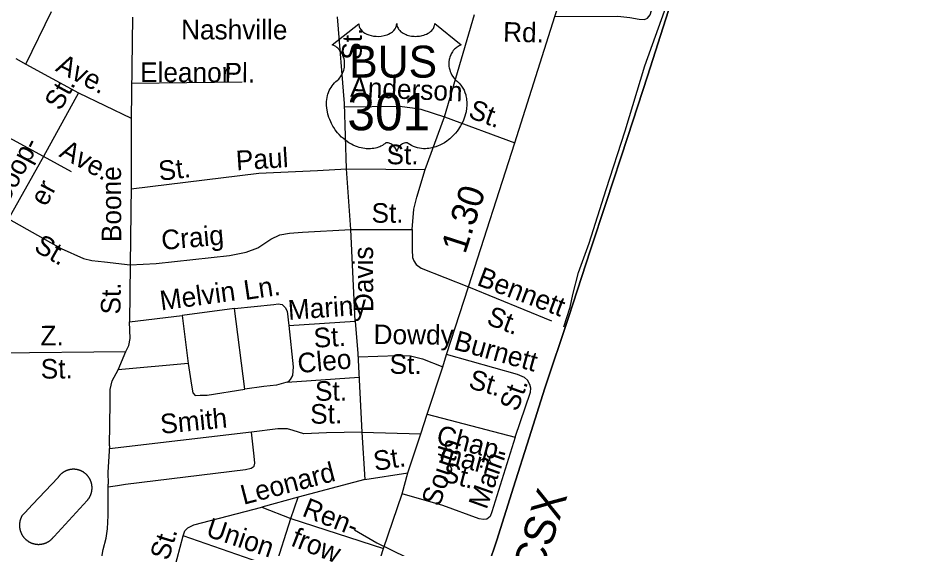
# Model space of a CAD drawing. Extents: x 2220236 to 2384410, y 720751 to 894131.
# Drawn here: x 2351588 to 2355954, y 791757 to 794328 of the extents above; entities that cross this region are included whole.
import ezdxf

# ---------------------------------------------------------------- set-up
doc = ezdxf.new("R2010")
doc.units = 0
doc.layers.add('Default', color=7, linetype='Continuous')

msp = doc.modelspace()

# ---------------------------------------------------------------- linework, layer by layer
at = {"layer": 'Default'}
for p, q in [((2351626.7, 794104.3), (2351750.7, 794358.9)), ((2353169.6, 793913.4), (2353137, 794334.5)), ((2353654.2, 793849.6), (2353800.3, 794344.9)), ((2352142.5, 794331.5), (2352136.8, 793843)), ((2351578.4, 794131.9), (2351626.7, 794104.3)), ((2351626.7, 794104.3), (2351880.9, 793965.7)), ((2351880.9, 793965.7), (2351711.2, 793658)), ((2351880.9, 793965.7), (2352136.8, 793843)), ((2353179.5, 793597.7), (2353169.6, 793913.4)), ((2351711.2, 793658), (2351402, 793824)), ((2352136.8, 793843), (2352136.8, 793515.1)), ((2353561.4, 793594.3), (2353654.2, 793849.6)), ((2353654.2, 793849.6), (2353995.7, 793723.4)), ((2351711.2, 793658), (2351541.6, 793355.6)), ((2351848.1, 793583.7), (2351711.2, 793658)), ((2353200.9, 793304), (2353179.5, 793597.7)), ((2353179.5, 793597.7), (2353561.4, 793594.3)), ((2352136.8, 793515.1), (2352132.1, 793132.4)), ((2353200.9, 793304), (2353498.8, 793303.6)), ((2353222.2, 792860.5), (2353200.9, 793304)), ((2352132.1, 793132.4), (2352128.6, 792857.3)), ((2353771.1, 793026.6), (2354173.9, 792861.9)), ((2352637.6, 792921.5), (2352383.7, 792888.1)), ((2352688.1, 792529.8), (2352637.6, 792921.5)), ((2352128.6, 792857.3), (2352383.7, 792888.1)), ((2352383.7, 792888.1), (2352413.5, 792654.2)), ((2352900.5, 792838.6), (2353222.2, 792860.5)), ((2353222.2, 792860.5), (2353235.2, 792703.4)), ((2351348.7, 792706), (2352110.3, 792713.1)), ((2352073.5, 792624.7), (2352110.3, 792713.1)), ((2353235.2, 792703.4), (2353254.7, 792323)), ((2352413.5, 792654.2), (2352073.5, 792624.7)), ((2352892.1, 792565.1), (2353241.1, 792588.8)), ((2353571.5, 792408.8), (2353996.8, 792297.9)), ((2352719.1, 792323), (2352030.9, 792241.7)), ((2353254.7, 792323), (2353540.8, 792314.5)), ((2353254.7, 792323), (2353269.5, 792093.3)), ((2353269.5, 792093.3), (2353477, 792125.8)), ((2353269.5, 792093.3), (2352946.4, 792008.2)), ((2351762.8, 791817.3), (2351922.8, 791990.9)), ((2352946.4, 792008.2), (2352769.1, 791959.2)), ((2352910.7, 791904), (2352946.4, 792008.2)), ((2352769.1, 791959.2), (2352910.7, 791904)), ((2352833.8, 791666.1), (2352910.7, 791904)), ((2352910.7, 791904), (2353358.8, 791758.5)), ((2352321.5, 791572.9), (2352389, 791820.9)), ((2352833.8, 791666.1), (2352389, 791820.9))]:
    msp.add_line(p, q, dxfattribs=at)
for points in [[(2353828.2, 791561.1), (2353908, 791798.6), (2353988.7, 792056.1), (2354064.7, 792295.5), (2354141.6, 792535.9), (2354255.5, 792877.9), (2354362.8, 793205.7), (2354437.8, 793434.7), (2354543.2, 793754.9), (2354639.1, 794046.6), (2354740.7, 794364.8), (2354855.5, 794713.5), (2354972.3, 795071.7), (2355085.3, 795428), (2355185, 795733), (2355317, 796125.4), (2355452.7, 796546.3), (2355542.9, 796832.3), (2355661.6, 797196.2), (2355741.4, 797441.3), (2355954, 798148.2)], [(2355954, 798148.2), (2355741.4, 797441.3), (2355661.6, 797196.2), (2355542.9, 796832.3), (2355452.7, 796546.3), (2355317, 796125.4), (2355185, 795733), (2355085.3, 795428), (2354972.3, 795071.7), (2354855.5, 794713.5), (2354740.7, 794364.8), (2354639.1, 794046.6), (2354543.2, 793754.9), (2354437.8, 793434.7), (2354362.8, 793205.7), (2354255.5, 792877.9), (2354141.6, 792535.9), (2354064.7, 792295.5), (2353988.7, 792056.1), (2353908, 791798.6), (2353828.2, 791561.1)], [(2353000.4, 790646), (2353049.1, 790801), (2353123.6, 791038.5), (2353207.2, 791284.8), (2353280.4, 791511.5), (2353358.8, 791758.5), (2353450.2, 792023.5), (2353477, 792125.8), (2353540.8, 792314.5), (2353571.5, 792408.8), (2353646.8, 792639.5), (2353664, 792697.9), (2353771.1, 793026.6), (2353995.7, 793723.4), (2354190.2, 794335.6), (2354323.4, 794739), (2354464.8, 795188), (2354608.5, 795632.2), (2354625.9, 795670.4), (2354758.9, 796083.8), (2354776.2, 796150.1), (2354878.2, 796485.2), (2354997.8, 796838.4), (2355117.9, 797165.9)], [(2354233.2, 792832.6), (2354233.3, 792833.1), (2354263.1, 792927), (2354276.4, 792989.2), (2354305, 793095.4), (2354355.2, 793237.9), (2354438.1, 793496.8), (2354530.7, 793781.9), (2354624.9, 794096.9), (2354742.9, 794426.2), (2354852.7, 794781.4), (2354968.4, 795138.7), (2355078.1, 795470.4), (2355089.9, 795510), (2355095.3, 795548.1), (2355096.5, 795572.8)], [(2354190.2, 794335.6), (2354494.1, 794337.2), (2354552.2, 794330), (2354598.3, 794322.5), (2354624.2, 794320.7), (2354638.1, 794326.9), (2354651.9, 794343.1), (2354732.8, 794606.1)], [(2352138.8, 794012.4), (2352675.2, 794018.7)], [(2353170.1, 793898.6), (2353437.6, 793900.7), (2353499.7, 793893.5), (2353539.9, 793885.9), (2353654.2, 793849.6)], [(2352136.8, 793500.7), (2352756, 793577.1), (2353039.4, 793590.3), (2353179.5, 793597.7)], [(2353498.8, 793303.6), (2353505.6, 793401.7), (2353521, 793459.7), (2353561.4, 793594.3)], [(2351541.6, 793355.6), (2351796.9, 793211.5), (2351905.1, 793162.9), (2351946.8, 793154), (2352007.8, 793148), (2352132.1, 793132.4)], [(2352132.1, 793132.4), (2352257.2, 793139.8), (2352613, 793178.6), (2352693.3, 793193.4), (2352749.9, 793214.3), (2352813.9, 793257.5), (2352857.1, 793278.4), (2352903.2, 793285.8), (2352967.2, 793290.3), (2353200.9, 793304)], [(2353498.8, 793303.6), (2353498, 793205.7), (2353500.5, 793167.8), (2353506.6, 793151.8), (2353516.9, 793133.8), (2353541.1, 793116.2), (2353771.1, 793026.6)], [(2352637.6, 792921.5), (2352828.1, 792941), (2352848.9, 792943.9), (2352868.3, 792941), (2352883.5, 792926.3), (2352891.9, 792908.4), (2352900.5, 792838.6)], [(2352110.3, 792713.1), (2352126, 792741.3), (2352131.6, 792775.4), (2352128.6, 792857.3)], [(2352900.5, 792838.6), (2352921.1, 792638.9), (2352917.6, 792597), (2352907.8, 792576.8), (2352897.8, 792566.7), (2352840.1, 792550), (2352780.1, 792543.3), (2352688.1, 792529.8)], [(2353236.6, 792686.5), (2353427.6, 792693), (2353490.1, 792691.4), (2353548, 792677.3), (2353646.8, 792639.5)], [(2353996.8, 792297.9), (2354072.1, 792516.8), (2354073.8, 792534.7), (2354067.7, 792552.7), (2354057.4, 792574.7), (2354043.3, 792586.5), (2354009, 792601.9), (2353664, 792697.9)], [(2352413.5, 792654.2), (2352428.4, 792549.9), (2352435.8, 792512.7), (2352446.2, 792499.3), (2352471.5, 792500.8), (2352504.3, 792500.8), (2352688.1, 792529.8)], [(2352031.9, 792256.3), (2352035.4, 792464.3), (2352034.6, 792528.3), (2352044.1, 792570.3), (2352073.5, 792624.7)], [(2353254.7, 792323), (2353082.9, 792319.6), (2352972.7, 792313.6), (2352921.1, 792330.5), (2352894.7, 792338.7), (2352846.7, 792338.2), (2352719.1, 792323)], [(2352025.5, 792057.5), (2352070.4, 792063.3), (2352109.5, 792071.2), (2352690.4, 792142.3), (2352718.1, 792148.3), (2352732, 792158.2), (2352736, 792172.1), (2352732.2, 792206.8), (2352719.1, 792323)], [(2353996.8, 792297.9), (2353884.2, 791936.7), (2353875.4, 791914.6), (2353860.4, 791901), (2353843.5, 791899), (2353822.7, 791903), (2353646.8, 791967.9), (2353450.2, 792023.5)], [(2352031.9, 792256.3), (2352023.5, 792128.4), (2352025.4, 792070.8)], [(2351907.8, 792127), (2351906.5, 792127.9), (2351905.2, 792128.7), (2351903.8, 792129.6), (2351902.5, 792130.4), (2351901.1, 792131.1), (2351899.7, 792131.9), (2351898.4, 792132.6), (2351896.9, 792133.3), (2351895.5, 792134), (2351894.1, 792134.7), (2351892.7, 792135.3), (2351891.2, 792135.9), (2351889.8, 792136.5), (2351888.3, 792137.1), (2351886.8, 792137.6), (2351885.3, 792138.1), (2351883.8, 792138.6), (2351882.3, 792139), (2351880.8, 792139.5), (2351879.3, 792139.9), (2351877.8, 792140.2), (2351876.2, 792140.6), (2351874.7, 792140.9), (2351873.2, 792141.2), (2351871.6, 792141.5), (2351870.1, 792141.7), (2351868.5, 792141.9), (2351866.9, 792142.1), (2351865.4, 792142.3), (2351863.8, 792142.4), (2351862.2, 792142.5), (2351860.7, 792142.6), (2351859.1, 792142.6), (2351857.5, 792142.6), (2351856, 792142.6), (2351854.4, 792142.6), (2351852.8, 792142.5), (2351851.3, 792142.5), (2351849.7, 792142.3), (2351848.1, 792142.2), (2351846.6, 792142), (2351845, 792141.8), (2351843.4, 792141.6), (2351841.9, 792141.4), (2351840.3, 792141.1), (2351838.8, 792140.8), (2351837.3, 792140.4), (2351835.7, 792140.1), (2351834.2, 792139.7), (2351832.7, 792139.3), (2351831.2, 792138.9), (2351829.7, 792138.4), (2351828.2, 792137.9), (2351826.7, 792137.4), (2351825.2, 792136.8), (2351823.8, 792136.3), (2351822.3, 792135.7), (2351820.9, 792135.1), (2351819.4, 792134.4), (2351818, 792133.8), (2351816.6, 792133.1), (2351815.2, 792132.3), (2351813.8, 792131.6), (2351812.5, 792130.8), (2351811.1, 792130), (2351809.8, 792129.2), (2351808.4, 792128.4), (2351807.1, 792127.5), (2351805.8, 792126.7), (2351804.5, 792125.7), (2351803.3, 792124.8), (2351802, 792123.9), (2351800.8, 792122.9), (2351799.5, 792121.9), (2351798.3, 792120.9), (2351797.2, 792119.9), (2351796, 792118.8), (2351794.9, 792117.7), (2351793.7, 792116.6), (2351792.6, 792115.5), (2351791.5, 792114.4), (2351790.5, 792113.2), (2351789.4, 792112.1), (2351788.4, 792110.9), (2351787.4, 792109.7), (2351786.4, 792108.4), (2351785.4, 792107.2), (2351784.5, 792106), (2351783.6, 792104.7), (2351782.7, 792103.4)], [(2351922.8, 791990.9), (2351923.8, 791992), (2351924.9, 791993.2), (2351925.9, 791994.4), (2351926.9, 791995.6), (2351927.9, 791996.8), (2351928.9, 791998.1), (2351929.8, 791999.3), (2351930.7, 792000.6), (2351931.6, 792001.9), (2351932.5, 792003.2), (2351933.3, 792004.5), (2351934.1, 792005.9), (2351934.9, 792007.2), (2351935.7, 792008.6), (2351936.5, 792010), (2351937.2, 792011.4), (2351937.9, 792012.8), (2351938.6, 792014.2), (2351939.3, 792015.6), (2351939.9, 792017.1), (2351940.5, 792018.5), (2351941.1, 792020), (2351941.6, 792021.4), (2351942.2, 792022.9), (2351942.7, 792024.4), (2351943.1, 792025.9), (2351943.6, 792027.4), (2351944, 792028.9), (2351944.4, 792030.4), (2351944.8, 792032), (2351945.1, 792033.5), (2351945.5, 792035), (2351945.7, 792036.6), (2351946, 792038.1), (2351946.2, 792039.7), (2351946.5, 792041.2), (2351946.6, 792042.8), (2351946.8, 792044.4), (2351946.9, 792045.9), (2351947, 792047.5), (2351947.1, 792049.1), (2351947.1, 792050.6), (2351947.2, 792052.2), (2351947.2, 792053.8), (2351947.1, 792055.3), (2351947.1, 792056.9), (2351947, 792058.5), (2351946.9, 792060), (2351946.7, 792061.6), (2351946.5, 792063.2), (2351946.3, 792064.7), (2351946.1, 792066.3), (2351945.9, 792067.8), (2351945.6, 792069.4), (2351945.3, 792070.9), (2351944.9, 792072.5), (2351944.6, 792074), (2351944.2, 792075.5), (2351943.8, 792077), (2351943.3, 792078.5), (2351942.9, 792080), (2351942.4, 792081.5), (2351941.9, 792083), (2351941.3, 792084.5), (2351940.7, 792086), (2351940.1, 792087.4), (2351939.5, 792088.8), (2351938.9, 792090.3), (2351938.2, 792091.7), (2351937.5, 792093.1), (2351936.8, 792094.5), (2351936.1, 792095.9), (2351935.3, 792097.3), (2351934.5, 792098.6), (2351933.7, 792100), (2351932.8, 792101.3), (2351932, 792102.6), (2351931.1, 792103.9), (2351930.2, 792105.2), (2351929.3, 792106.5), (2351928.3, 792107.7), (2351927.3, 792108.9), (2351926.3, 792110.2), (2351925.3, 792111.4), (2351924.3, 792112.5), (2351923.2, 792113.7), (2351922.2, 792114.8), (2351921.1, 792116), (2351919.9, 792117.1), (2351918.8, 792118.2), (2351917.7, 792119.2), (2351916.5, 792120.3), (2351915.3, 792121.3), (2351914.1, 792122.3), (2351912.9, 792123.3), (2351911.6, 792124.2), (2351910.4, 792125.2), (2351909.1, 792126.1), (2351907.8, 792127)], [(2351782.7, 792103.4), (2351658.1, 791971.8), (2351621.8, 791932), (2351608.9, 791919.4)], [(2351987.6, 791678.5), (2352001.5, 791754.6), (2352015.3, 791808.3), (2352022.2, 791855), (2352025.7, 791919.1), (2352025.7, 792031.6), (2352025.4, 792070.8)], [(2352389, 791820.9), (2352396.6, 791844.8), (2352410.5, 791859), (2352440.3, 791873.4), (2352769.1, 791959.2)], [(2351608.9, 791919.4), (2351608, 791918), (2351607.2, 791916.6), (2351606.5, 791915.2), (2351605.7, 791913.8), (2351605, 791912.4), (2351604.3, 791910.9), (2351603.6, 791909.5), (2351603, 791908), (2351602.4, 791906.5), (2351601.8, 791905), (2351601.2, 791903.5), (2351600.6, 791902), (2351600.1, 791900.5), (2351599.6, 791899), (2351599.2, 791897.4), (2351598.7, 791895.9), (2351598.3, 791894.3), (2351597.9, 791892.7), (2351597.6, 791891.2), (2351597.3, 791889.6), (2351597, 791888), (2351596.7, 791886.4), (2351596.4, 791884.9), (2351596.2, 791883.3), (2351596, 791881.7), (2351595.9, 791880.1), (2351595.7, 791878.5), (2351595.6, 791876.9), (2351595.5, 791875.3), (2351595.5, 791873.7), (2351595.5, 791872), (2351595.5, 791870.4), (2351595.5, 791868.8), (2351595.6, 791867.2), (2351595.6, 791865.6), (2351595.8, 791864), (2351595.9, 791862.4), (2351596.1, 791860.8), (2351596.3, 791859.2), (2351596.5, 791857.6), (2351596.8, 791856), (2351597, 791854.5), (2351597.3, 791852.9), (2351597.7, 791851.3), (2351598, 791849.7), (2351598.4, 791848.2), (2351598.9, 791846.6), (2351599.3, 791845.1), (2351599.8, 791843.5), (2351600.3, 791842), (2351600.8, 791840.5), (2351601.4, 791839), (2351601.9, 791837.5), (2351602.5, 791836), (2351603.2, 791834.5), (2351603.8, 791833.1), (2351604.5, 791831.6), (2351605.2, 791830.2), (2351605.9, 791828.7), (2351606.7, 791827.3), (2351607.5, 791825.9), (2351608.3, 791824.5), (2351609.1, 791823.1), (2351610, 791821.8), (2351610.8, 791820.4), (2351611.7, 791819.1), (2351612.7, 791817.8), (2351613.6, 791816.5), (2351614.6, 791815.2), (2351615.6, 791813.9), (2351616.6, 791812.7), (2351617.6, 791811.4), (2351618.7, 791810.2), (2351619.7, 791809), (2351620.8, 791807.9), (2351621.9, 791806.7), (2351623.1, 791805.6), (2351624.2, 791804.4), (2351625.4, 791803.3), (2351626.6, 791802.3), (2351627.8, 791801.2), (2351629.1, 791800.2), (2351630.3, 791799.2), (2351631.6, 791798.2), (2351632.9, 791797.2), (2351634.2, 791796.3), (2351635.5, 791795.3), (2351636.8, 791794.4), (2351638.1, 791793.6), (2351639.5, 791792.7), (2351640.9, 791791.9), (2351642.3, 791791.1), (2351643.7, 791790.3), (2351645.1, 791789.5), (2351646.5, 791788.8), (2351648, 791788.1), (2351649.4, 791787.4), (2351650.9, 791786.8), (2351652.4, 791786.1)], [(2353218.4, 791848.7), (2353327, 791786.1), (2353469.9, 791717.7), (2353536.3, 791684.6), (2353582.6, 791647.1), (2353633.8, 791602.2), (2353679.2, 791551.7), (2353708.4, 791493.2), (2353723.5, 791444.7), (2353736.9, 791404.4), (2353745.1, 791363.3), (2353738.6, 791305.5)], [(2351652.4, 791786.1), (2351653.9, 791785.5), (2351655.4, 791784.9), (2351656.9, 791784.4), (2351658.4, 791783.9), (2351659.9, 791783.4), (2351661.5, 791782.9), (2351663, 791782.4), (2351664.6, 791782), (2351666.1, 791781.6), (2351667.7, 791781.3), (2351669.3, 791780.9), (2351670.8, 791780.6), (2351672.4, 791780.3), (2351674, 791780.1), (2351675.6, 791779.9), (2351677.2, 791779.7), (2351678.8, 791779.5), (2351680.4, 791779.3), (2351682, 791779.2), (2351683.6, 791779.1), (2351685.2, 791779.1), (2351686.8, 791779), (2351688.4, 791779), (2351690, 791779.1), (2351691.6, 791779.1), (2351693.2, 791779.2), (2351694.8, 791779.3), (2351696.4, 791779.4), (2351698, 791779.6), (2351699.6, 791779.8), (2351701.2, 791780), (2351702.8, 791780.2), (2351704.4, 791780.5), (2351706, 791780.8), (2351707.6, 791781.1), (2351709.1, 791781.5), (2351710.7, 791781.9), (2351712.2, 791782.3), (2351713.8, 791782.7), (2351715.3, 791783.2), (2351716.9, 791783.7), (2351718.4, 791784.2), (2351719.9, 791784.7), (2351721.4, 791785.3), (2351722.9, 791785.9), (2351724.4, 791786.5), (2351725.8, 791787.2), (2351727.3, 791787.8), (2351728.8, 791788.5), (2351730.2, 791789.3), (2351731.6, 791790), (2351733, 791790.8), (2351734.4, 791791.6), (2351735.8, 791792.4), (2351737.2, 791793.3), (2351738.5, 791794.1), (2351739.9, 791795), (2351741.2, 791795.9), (2351742.5, 791796.9), (2351743.8, 791797.8), (2351745, 791798.8), (2351746.3, 791799.8), (2351747.5, 791800.8), (2351748.8, 791801.9), (2351750, 791803), (2351751.1, 791804), (2351752.3, 791805.2), (2351753.4, 791806.3), (2351754.6, 791807.4), (2351755.7, 791808.6), (2351756.8, 791809.8), (2351757.8, 791811), (2351758.9, 791812.2), (2351759.9, 791813.5), (2351760.9, 791814.7), (2351761.9, 791816), (2351762.8, 791817.3)]]:
    msp.add_lwpolyline(points, dxfattribs=at)
msp.add_lwpolyline([(2353239.4, 794300.5), (2353239.7, 794295.2), (2353241, 794288.9), (2353242, 794285.6), (2353245, 794279.4), (2353249.8, 794272), (2353256.6, 794264.8), (2353264.3, 794258.5), (2353269.5, 794255.2), (2353278.2, 794250.5), (2353288.2, 794246.3), (2353299.3, 794243.1), (2353310.6, 794240.8), (2353323, 794239.4), (2353335.2, 794239.2), (2353348.4, 794240.2), (2353363, 794243), (2353369.8, 794244.8), (2353377.3, 794247.3), (2353384.3, 794250.2), (2353391.9, 794254.3), (2353398.1, 794258.3), (2353402.9, 794261.8), (2353409.7, 794268.3), (2353415.2, 794275.1), (2353417.5, 794278.9), (2353419.4, 794282.5), (2353422.1, 794290.3), (2353422.9, 794293.7), (2353423.4, 794300.8), (2353423.9, 794294.8), (2353424.5, 794291.1), (2353425.5, 794287.5), (2353427, 794283.6), (2353429.7, 794278.1), (2353432.8, 794273.6), (2353438.5, 794266.8), (2353442.1, 794263.5), (2353445.3, 794260.8), (2353454.1, 794254.8), (2353464.3, 794249.6), (2353469.3, 794247.4), (2353474.5, 794245.6), (2353481, 794243.6), (2353487.7, 794242), (2353494.4, 794240.9), (2353501.3, 794239.9), (2353508.3, 794239.4), (2353513.9, 794239.2), (2353520.9, 794239.3), (2353527.4, 794239.7), (2353534, 794240.4), (2353541.3, 794241.6), (2353547.1, 794242.9), (2353554.9, 794245), (2353561.9, 794247.5), (2353568, 794250.2), (2353576, 794254.3), (2353582.5, 794258.4), (2353587.2, 794262.2), (2353592.8, 794267.3), (2353598.1, 794273.5), (2353601.2, 794278), (2353603.4, 794282.6), (2353605.5, 794287.5), (2353606.7, 794292.6), (2353607.3, 794297.1), (2353607.5, 794300.9), (2353736, 794198.5), (2353733, 794197.3), (2353726, 794193.9), (2353720.5, 794190.7), (2353711.6, 794184.4), (2353707.8, 794181), (2353704, 794177.4), (2353700.6, 794173.6), (2353697.5, 794170.1), (2353693.8, 794164.9), (2353690.4, 794159.7), (2353687.1, 794154), (2353684.8, 794149.1), (2353680.8, 794138.8), (2353678.9, 794132.2), (2353677.7, 794126.7), (2353676.2, 794115.2), (2353675.8, 794109.7), (2353675.8, 794104.3), (2353676.1, 794098.6), (2353676.6, 794093.2), (2353677.6, 794087.5), (2353678.5, 794082.5), (2353680.1, 794076.3), (2353682.4, 794069.2), (2353685.2, 794062.2), (2353691.1, 794051.1), (2353698.6, 794039.7), (2353704, 794033.3), (2353709.4, 794027.8), (2353717.3, 794021.1), (2353721.6, 794017.3), (2353726.5, 794012.4), (2353734.6, 794003), (2353737.8, 793998.6), (2353741.1, 793993.7), (2353744.2, 793988.6), (2353747.2, 793983.1), (2353749.6, 793978.3), (2353754.2, 793967.3), (2353757.5, 793956.6), (2353759, 793951), (2353761.4, 793938.4), (2353762.3, 793932.1), (2353763.3, 793919.8), (2353763.3, 793904.9), (2353762.2, 793890.8), (2353759.5, 793874.3), (2353757.3, 793864.4), (2353753.9, 793853), (2353750.7, 793843), (2353744.8, 793828.4), (2353739.6, 793817.7), (2353732.8, 793805.3), (2353728.2, 793797.7), (2353722.8, 793789.7), (2353716, 793780.4), (2353708.1, 793770.5), (2353698.7, 793760.1), (2353691, 793752.4), (2353681, 793743.5), (2353674.9, 793738.5), (2353666.2, 793731.9), (2353654.4, 793724), (2353642.7, 793717.3), (2353632.7, 793712.2), (2353623.9, 793708.4), (2353612.5, 793704), (2353593.5, 793698.8), (2353586.6, 793697.4), (2353578.4, 793696.1), (2353570.8, 793695.4), (2353563.3, 793694.9), (2353553.3, 793694.9), (2353543.3, 793695.7), (2353533.9, 793697), (2353524.1, 793699.1), (2353513.9, 793702.1), (2353504.6, 793705.8), (2353495.2, 793710.4), (2353479.2, 793720.4), (2353474.6, 793722.9), (2353472.1, 793723.6), (2353465.9, 793723.9), (2353460.1, 793722.7), (2353454.2, 793720.3), (2353450.6, 793718.4), (2353445.9, 793715.3), (2353442.3, 793712.4), (2353437.8, 793708.2), (2353434.8, 793704.7), (2353432.5, 793702), (2353428, 793694.9), (2353426.4, 793691.6), (2353424.7, 793687.2), (2353423.3, 793680.9), (2353421.3, 793688.9), (2353418.9, 793694.2), (2353416.2, 793698.8), (2353413.3, 793702.8), (2353408.8, 793708), (2353404.8, 793711.9), (2353400, 793715.8), (2353394.8, 793718.9), (2353390.6, 793721.1), (2353386.9, 793722.5), (2353382.2, 793723.6), (2353378.4, 793723.9), (2353375.3, 793723.9), (2353371, 793722.9), (2353365.2, 793718.7), (2353359.7, 793714.9), (2353353.7, 793711.2), (2353346.6, 793707.4), (2353341.3, 793704.9), (2353335.1, 793702.5), (2353327.8, 793700.1), (2353319.9, 793698), (2353311.8, 793696.4), (2353304.6, 793695.3), (2353297, 793694.6), (2353290.1, 793694.4), (2353282.8, 793694.5), (2353276.1, 793695), (2353268.3, 793695.7), (2353258.5, 793697.1), (2353250.5, 793698.9), (2353242, 793701.2), (2353233.2, 793704), (2353223.9, 793707.5), (2353212.2, 793712.6), (2353204.1, 793716.8), (2353191.2, 793724.2), (2353176.2, 793734.6), (2353164.9, 793743.8), (2353156.5, 793751.3), (2353144.3, 793763.8), (2353137.1, 793771.9), (2353125.9, 793786.5), (2353118.6, 793797), (2353114, 793804.8), (2353107.1, 793817.3), (2353103.4, 793825.1), (2353098.5, 793836.5), (2353094.7, 793846.9), (2353091.5, 793856.8), (2353089.8, 793863.1), (2353087.4, 793874.1), (2353085.9, 793881.9), (2353084.4, 793892.6), (2353083.6, 793904), (2353083.5, 793914.4), (2353083.8, 793923), (2353084.7, 793933.1), (2353086.4, 793943.8), (2353088.5, 793953), (2353090.4, 793959.7), (2353093.1, 793967.7), (2353096.7, 793976.6), (2353101, 793985.1), (2353105, 793992.2), (2353110.1, 793999.8), (2353115.1, 794006.2), (2353121.7, 794013.4), (2353128.5, 794019.9), (2353134.8, 794025), (2353142.2, 794032.3), (2353146.1, 794036.7), (2353150.8, 794042.9), (2353154.5, 794048.6), (2353157.5, 794053.6), (2353161.4, 794061.2), (2353163.7, 794066.8), (2353166.7, 794075.5), (2353168.2, 794081.5), (2353169.7, 794089.4), (2353170.7, 794096.7), (2353171.1, 794105.9), (2353170.8, 794113.5), (2353169.8, 794122.4), (2353168.2, 794130.9), (2353166.2, 794138.4), (2353163, 794146.9), (2353160, 794153.1), (2353155.1, 794161.6), (2353149.6, 794169.4), (2353144, 794175.8), (2353138.3, 794181.5), (2353132.8, 794185.7), (2353127.6, 794189.4), (2353121.1, 794193.4), (2353114.8, 794196.5), (2353110.8, 794198.1)], close=True, dxfattribs=at)

# ---------------------------------------------------------------- texts
for s, height, rotation, p in [('Nashville', 95, 359.9064, (2352378.3, 794224.7)), ('Rd.', 95, 358.6339, (2353938, 794213.8)), ('St.', 95, 89.1599, (2353252.9, 794125)), ('Ave.', 95, 332.6015, (2351765.7, 794074.2)), ('Eleanor', 95, 359.9064, (2352179.7, 794017.7)), ('Pl.', 95, 359.9064, (2352589.2, 794015.9)), ('Anderson', 95, 357.5899, (2353197.1, 793947.2)), ('St.', 95, 60.8637, (2351794.3, 793874.5)), ('St.', 95, 339.7989, (2353765.2, 793847.3)), ('Coop-', 95, 62.1073, (2351532.6, 793414.5)), ('Ave.', 95, 331.5095, (2351782.9, 793659.5)), ('Paul', 95, 3.7089, (2352647.2, 793590.1)), ('St.', 95, 359.4896, (2353373.8, 793620)), ('St.', 95, 6.9023, (2352274.5, 793539.3)), ('Boone', 95, 90.2317, (2352088.8, 793243)), ('er', 95, 62.1073, (2351724.9, 793410.8)), ('1.30', 125, 72.1351, (2353755.3, 793181.4)), ('St.', 95, 359.923, (2353301.1, 793336.6)), ('Craig', 95, 5.0993, (2352286.9, 793204.4)), ('St.', 95, 330.216, (2351660.2, 793203.1)), ('Davis', 95, 90.2317, (2353309.8, 792904)), ('Bennett', 95, 339.239, (2353807, 793036.1)), ('St.', 95, 89.1599, (2352084.5, 792891.8)), ('Melvin', 95, 7.7309, (2352282.2, 792911.3)), ('Ln.', 95, 8.3123, (2352689.2, 792962.2)), ('Mariny', 95, 3.8944, (2352899.3, 792866.4)), ('St.', 95, 339.239, (2353853.1, 792846.8)), ('Z.', 95, 0.5343, (2351697.2, 792742.1)), ('St.', 95, 3.8944, (2353023.9, 792730.6)), ('Dowdy', 95, 359.5909, (2353311, 792748.9)), ('Burnett', 95, 344.4501, (2353694.6, 792724.6)), ('St.', 95, 0.5343, (2351698.7, 792581.5)), ('Cleo', 95, 5.0993, (2352947, 792608.3)), ('St.', 95, 359.5909, (2353388.5, 792605)), ('St.', 95, 344.4501, (2353766.6, 792536.7)), ('St.', 95, 0.6316, (2353027.8, 792473.9)), ('St.', 95, 70.0177, (2354008.2, 792417.8)), ('St.', 95, 0.6316, (2353004.4, 792362.9)), ('Smith', 95, 5.5928, (2352282.3, 792313.8)), ('Chap-', 95, 345.3852, (2353609.7, 792266.8)), ('South', 95, 71.3194, (2353630.9, 791957.8)), ('St.', 95, 8.9017, (2353318, 792134.1)), ('man', 95, 345.3852, (2353625.7, 792179.9)), ('Main', 95, 70.4524, (2353858.2, 791944.6)), ('Leonard', 95, 14.6253, (2352681.2, 791970.2)), ('St.', 95, 345.3852, (2353636.8, 792086.7)), ('CSX', 150, 72.1053, (2354124.7, 791623.2)), ('Ren-', 95, 338.4438, (2352960, 791918.4)), ('Union', 95, 341.3463, (2352493.8, 791820.2)), ('frow', 95, 338.4438, (2352905, 791774.7)), ('St.', 95, 73.1306, (2352317, 791696.5))]:
    msp.add_text(s, height=height, rotation=rotation, dxfattribs=at).set_placement(p)
for s, height, p in [('BUS', 155, (2353193.1, 794039.2)), ('301', 180, (2353184.2, 793784.4))]:
    msp.add_text(s, height=height, dxfattribs=at).set_placement(p)

doc.saveas('drawing.dxf')
